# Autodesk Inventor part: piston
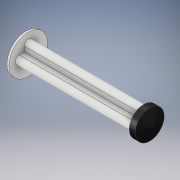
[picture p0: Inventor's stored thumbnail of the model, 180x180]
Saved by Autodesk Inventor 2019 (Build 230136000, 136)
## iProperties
Created: 2020-11
Part Number: piston
Material: PVC, Unplasticized
Document SubType Name: Modeling
Designer: bianc
Density: 1.29 g/cm^3
Appearance: Smooth - White
Author: bianc
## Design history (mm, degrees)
sketch "Sketch2"
  geometry: L1 (0, 0)-(-3, 0); L2 (-3, 0)-(-3, 7.144); L3 (-3, 7.144)-(0, 7.144); L4 (0, 7.144)-(0, 0); L5 (0, 0)-(2, 0); L6 (2, 0)-(0, 7.144)
  constraints: 12 end point, 2 horizontal, 2 parallel, 1 perpendicular
  dimensions: "d4" = 7.144 distance of L1.end L2.end; "d5" = 3 distance of L2.end L3.end; "d6" = 2 distance of L1.start L5.end
revolve "Revolution2" sketch "Sketch2" stored, may be unused: angle "d7" = 90 deg
sketch "Sketch3"
  geometry: L1 (0, 0)-(-15.744, 0); L2 (0, 0)-(0, 9.99); L3 (-4.5, -2)-(-2, -2); L4 (-4.5, 2)-(-2, 2); L5 (-2, 2)-(-2, 4.5); L6 (0, 0)-(0, -9.99); L7 (2, -2)-(2, -4.5); L8 (4.5, 2)-(2, 2); L9 (4.5, -2)-(2, -2); L10 (-2, -4.5)-(-2, -2); L11 (2, 2)-(2, 4.5); A1 r 2 centre (-4.5, 0) between (-4.5, 2) and (-4.5, -2); A2 r 2 centre (0, 4.5) between (2, 4.5) and (-2, 4.5); A3 r 2 centre (0, -4.5) between (-2, -4.5) and (2, -4.5); A4 r 2 centre (4.5, 0) between (4.5, -2) and (4.5, 2); 3 further points
  constraints: 22 end point, 9 symmetric about line, 8 point on circle, 4 centre point, 3 horizontal, 3 tangent, 3 vertical, 1 perpendicular, 1 point on line, 2 other
  dimensions: "d8" = 2 distance between parallel lines of L1 L3; "d9" = 2 distance between parallel lines of L4 L1; "d10" = 2 distance between parallel lines of L2 L5; "d12" = 4.5 distance of L1.start A1.centre; "d13" = 4.5 distance of A2.centre L1.start
extrude "Extrusion1" join sketch "Sketch3" distance "d14" = 57.15; taper "d15" = 0 deg
sketch "Sketch4"
  geometry: C1 r 9.525 at (0, 0); 1 further point
  constraints: 1 centre point, 1 coincident
  dimensions: "d16" = 19.05 diameter of C1
extrude "Extrusion2" join sketch "Sketch4" distance "d17" = 1; taper "d18" = 0 deg
body "Solid2"
